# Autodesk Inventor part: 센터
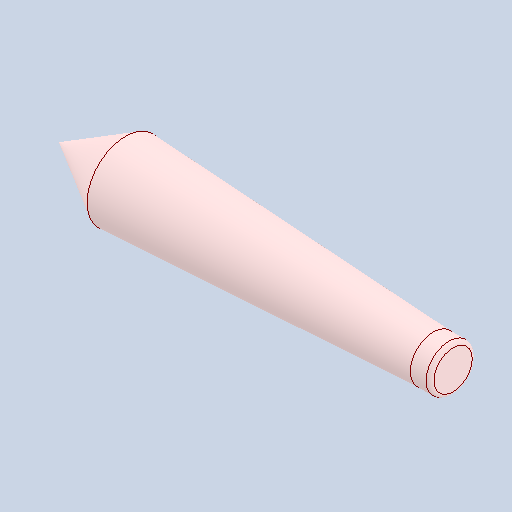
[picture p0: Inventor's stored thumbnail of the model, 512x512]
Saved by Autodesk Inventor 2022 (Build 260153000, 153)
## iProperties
Created: 2024-07
Part Number: 센터
Material: 강철, 합금
Document SubType Name: Modeling
Designer: PC-01
Density: 7.73 g/cm^3
Appearance: 기본값
Author: jhkim
Sending System: Autodesk Inventor 2025
Preprocessor: ST-DEVELOPER v20
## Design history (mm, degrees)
feature "솔리드1"
node "솔리드2"
